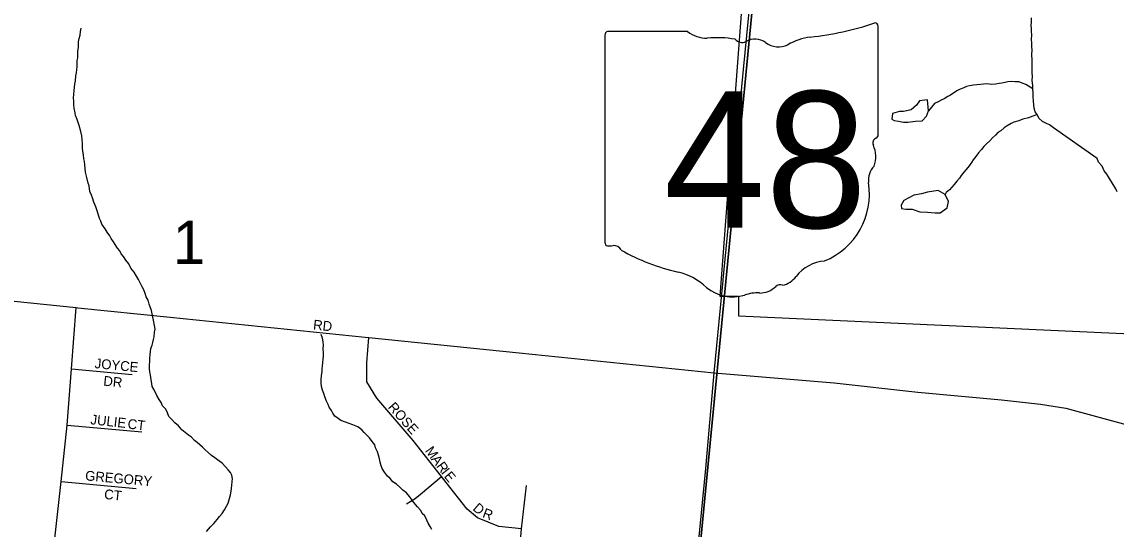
# Model space of a CAD drawing. Extents: x 0 to 1064, y 0 to 440.
# Drawn here: x 235.6 to 252.5, y 261.54 to 269.38 of the extents above; entities that cross this region are included whole.
import ezdxf

# ---------------------------------------------------------------- set-up
doc = ezdxf.new("R2010")
doc.units = 0
for name, color, linetype in [('GM_X_City_Street', 7, 'Continuous'), ('GM_X_City_Street_Text', 7, 'Continuous'), ('GM_X_Corporation', 7, 'Continuous'), ('GM_X_Minor_Lake', 7, 'Continuous'), ('GM_X_Minor_River', 7, 'Continuous'), ('GM_X_Section', 7, 'Continuous'), ('GM_X_Section_Text', 7, 'Continuous'), ('GM_X_State_Location', 7, 'Continuous'), ('GM_X_State_Route', 7, 'Continuous'), ('GM_X_State_Shield', 7, 'Continuous')]:
    doc.layers.add(name, color=color, linetype=linetype)

msp = doc.modelspace()

# ---------------------------------------------------------------- linework, layer by layer
at = {"layer": 'GM_X_City_Street'}
for points in [[(231.391, 265.48), (236.44, 264.965), (236.464, 264.962)], [(238.235, 258.707), (238.25, 258.748), (237.06, 259.196), (236.641, 259.365), (236.441, 259.452), (236.269, 259.569), (236.095, 259.825), (236.019, 260.045), (236.019, 260.414), (236.039, 260.725), (236.108, 261.4), (236.204, 262.278), (236.297, 263.152), (236.367, 264.019), (236.44, 264.965)], [(236.464, 264.962), (237.891, 264.817)], [(237.891, 264.817), (240.903, 264.51)], [(240.903, 264.51), (240.957, 264.504), (243.281, 264.267)], [(243.316, 261.548), (242.964, 261.585), (242.634, 261.72), (242.475, 261.854), (242.154, 262.266), (242.08, 262.356), (241.643, 262.912), (241.083, 263.566), (240.926, 263.818), (240.926, 264.113), (240.957, 264.504)], [(243.281, 264.267), (246.293, 263.96)], [(236.367, 264.019), (237.305, 263.93)], [(246.293, 263.96), (246.293, 263.96), (248.143, 263.801), (249.438, 263.657), (250.728, 263.54), (251.332, 263.475), (251.723, 263.41), (252.67, 263.153)], [(236.297, 263.152), (237.453, 263.047)], [(236.204, 262.278), (237.366, 262.171)], [(241.539, 261.937), (241.673, 262.019), (241.756, 262.085), (242.08, 262.356)], [(242.808, 256.231), (243.002, 258.326), (243.231, 260.605), (243.316, 261.548), (243.392, 262.217)]]:
    msp.add_lwpolyline(points, dxfattribs=at)
at = {"layer": 'GM_X_Corporation'}
msp.add_lwpolyline([(233.933, 272.908), (238.971, 272.631), (238.971, 271.725), (246.846, 271.347), (246.376, 265.143), (246.668, 265.143), (246.668, 264.837), (253.955, 264.502)], dxfattribs=at)
at = {"layer": 'GM_X_Minor_Lake'}
for points in [[(249.215, 267.994), (249.154, 267.996), (249.044, 267.962), (249.035, 267.877), (249.071, 267.858), (249.138, 267.844), (249.217, 267.83), (249.284, 267.828), (249.4, 267.844), (249.504, 267.853), (249.572, 267.925), (249.599, 268.003), (249.594, 268.064)], [(249.585, 268.174), (249.462, 268.158), (249.418, 268.093), (249.331, 268.022), (249.215, 267.994)], [(249.594, 268.064), (249.585, 268.174)], [(249.372, 266.701), (249.218, 266.619), (249.179, 266.547), (249.184, 266.498), (249.251, 266.485), (249.349, 266.488), (249.469, 266.443), (249.585, 266.44), (249.706, 266.431), (249.779, 266.429), (249.891, 266.506), (249.911, 266.603), (249.859, 266.713)], [(249.859, 266.713), (249.751, 266.777), (249.586, 266.75), (249.494, 266.722), (249.372, 266.701)]]:
    msp.add_lwpolyline(points, dxfattribs=at)
at = {"layer": 'GM_X_Minor_River'}
for points in [[(252.205, 267.268), (251.533, 267.745), (251.468, 267.789), (251.426, 267.809), (251.36, 267.841), (251.306, 267.891), (251.278, 267.947), (251.249, 267.99), (251.232, 268.045), (251.228, 268.094), (251.224, 268.161), (251.22, 268.222), (251.216, 268.277), (251.212, 268.344), (251.213, 268.392), (251.204, 268.477), (251.206, 268.538), (251.202, 268.593), (251.203, 268.641), (251.2, 268.72), (251.202, 268.793), (251.199, 268.872), (251.201, 268.945), (251.197, 268.994), (251.199, 269.06), (251.194, 269.103), (251.197, 269.182), (251.192, 269.224), (251.194, 269.273), (251.189, 269.328), (251.191, 269.376), (251.193, 269.443)], [(236.526, 267.62), (236.509, 267.687), (236.482, 267.779), (236.455, 267.871), (236.426, 267.932), (236.422, 267.975), (236.406, 268.048), (236.401, 268.097), (236.403, 268.152), (236.399, 268.206), (236.4, 268.255), (236.409, 268.321), (236.41, 268.364), (236.418, 268.424), (236.426, 268.467), (236.434, 268.545), (236.442, 268.594), (236.45, 268.642), (236.451, 268.684), (236.453, 268.739), (236.454, 268.781), (236.462, 268.824), (236.463, 268.866), (236.465, 268.927), (236.473, 268.981), (236.475, 269.03), (236.476, 269.072), (236.484, 269.121), (236.498, 269.175), (236.506, 269.229), (236.513, 269.284)], [(251.212, 268.344), (251.105, 268.414), (251.05, 268.434), (251.002, 268.453), (250.941, 268.455), (250.881, 268.457), (250.826, 268.453), (250.783, 268.442), (250.734, 268.431), (250.691, 268.426), (250.636, 268.416), (250.581, 268.412), (250.538, 268.419), (250.496, 268.42), (250.453, 268.416), (250.404, 268.411), (250.349, 268.407), (250.294, 268.402), (250.233, 268.392), (250.19, 268.381), (250.147, 268.358), (250.091, 268.342), (250.048, 268.319), (249.992, 268.284), (249.942, 268.249), (249.899, 268.226), (249.843, 268.192), (249.799, 268.169), (249.75, 268.146), (249.694, 268.117), (249.599, 268.003)], [(251.278, 267.947), (251.148, 267.896), (251.056, 267.875), (250.995, 267.852), (250.921, 267.83), (250.877, 267.807), (250.815, 267.773), (250.772, 267.744), (250.716, 267.697), (250.672, 267.668), (250.634, 267.627), (250.59, 267.586), (250.546, 267.544), (250.496, 267.497), (250.458, 267.456), (250.42, 267.409), (250.375, 267.355), (250.331, 267.302), (250.293, 267.249), (250.267, 267.207), (250.229, 267.154), (250.184, 267.1), (250.146, 267.059), (250.108, 267.005), (250.082, 266.964), (250.038, 266.917), (250, 266.869), (249.962, 266.828), (249.924, 266.786), (249.874, 266.746), (249.859, 266.713)], [(238.844, 262.217), (238.846, 262.278), (238.853, 262.32), (238.843, 262.375), (238.82, 262.418), (238.785, 262.462), (238.744, 262.505), (238.691, 262.562), (238.619, 262.613), (238.578, 262.644), (238.53, 262.682), (238.477, 262.726), (238.43, 262.77), (238.388, 262.808), (238.347, 262.846), (238.306, 262.883), (238.264, 262.915), (238.217, 262.965), (238.175, 262.997), (238.069, 263.079), (238.016, 263.141), (237.962, 263.185), (237.91, 263.242), (237.868, 263.285), (237.846, 263.341), (237.823, 263.396), (237.77, 263.446), (237.748, 263.502), (237.719, 263.545), (237.684, 263.607), (237.644, 263.693), (237.61, 263.749), (237.605, 263.791), (237.59, 263.883), (237.585, 263.926), (237.574, 263.968), (237.57, 264.023), (237.572, 264.078), (237.574, 264.139), (237.575, 264.181), (237.583, 264.241), (237.585, 264.29), (237.592, 264.332), (237.612, 264.386), (237.62, 264.429), (237.633, 264.471), (237.641, 264.513), (237.649, 264.585), (237.657, 264.634), (237.647, 264.689), (237.631, 264.774), (237.62, 264.817), (237.6, 264.921), (237.583, 264.976), (237.566, 265.019), (237.55, 265.08), (237.521, 265.13), (237.505, 265.185), (237.482, 265.24), (237.459, 265.284), (237.436, 265.327), (237.402, 265.401), (237.367, 265.45), (237.333, 265.512), (237.28, 265.574), (237.252, 265.642), (237.205, 265.698), (237.17, 265.754), (237.135, 265.798), (237.112, 265.841), (237.077, 265.884), (237.042, 265.94), (237.013, 265.983), (236.979, 266.033), (236.956, 266.076), (236.915, 266.132), (236.886, 266.182), (236.834, 266.256), (236.817, 266.299), (236.8, 266.342), (236.772, 266.428), (236.739, 266.52), (236.711, 266.594), (236.689, 266.661), (236.672, 266.704), (236.649, 266.76), (236.64, 266.845), (236.623, 266.888), (236.602, 266.974), (236.591, 267.017), (236.58, 267.059), (236.576, 267.114), (236.572, 267.169), (236.567, 267.224), (236.556, 267.266), (236.552, 267.327), (236.542, 267.382), (236.538, 267.431), (236.534, 267.504), (236.53, 267.559), (236.526, 267.62)], [(252.517, 266.755), (252.494, 266.798), (252.437, 266.891), (252.414, 266.934), (252.379, 266.984), (252.356, 267.027), (252.315, 267.077), (252.281, 267.151), (252.228, 267.213), (252.205, 267.268)], [(241.933, 261.539), (241.904, 261.582), (241.875, 261.637), (241.853, 261.681), (241.824, 261.748), (241.783, 261.786), (241.76, 261.829), (241.707, 261.886), (241.655, 261.954), (241.614, 262.004), (241.584, 262.047), (241.538, 262.103), (241.484, 262.147), (241.437, 262.191), (241.384, 262.236), (241.33, 262.274), (241.289, 262.324), (241.248, 262.361), (241.201, 262.423), (241.166, 262.479), (241.15, 262.522), (241.133, 262.577), (241.123, 262.632), (241.106, 262.687), (241.09, 262.737), (241.061, 262.798), (241.051, 262.847), (241.01, 262.897), (240.969, 262.953), (240.928, 262.997), (240.886, 263.034), (240.851, 263.078), (240.786, 263.122), (240.708, 263.155), (240.654, 263.175), (240.599, 263.195), (240.527, 263.221), (240.486, 263.253), (240.432, 263.291), (240.403, 263.335), (240.38, 263.378), (240.345, 263.427), (240.328, 263.47), (240.306, 263.52), (240.277, 263.587), (240.261, 263.637), (240.244, 263.692), (240.228, 263.747), (240.224, 263.802), (240.219, 263.856), (240.227, 263.911), (240.235, 263.977), (240.237, 264.02), (240.244, 264.062), (240.246, 264.117), (240.254, 264.171), (240.255, 264.213), (240.257, 264.268), (240.253, 264.329), (240.255, 264.384), (240.251, 264.438), (240.24, 264.493), (240.224, 264.548)], [(238.449, 261.507), (238.512, 261.578), (238.563, 261.631), (238.613, 261.69), (238.652, 261.737), (238.69, 261.785), (238.728, 261.844), (238.76, 261.898), (238.786, 261.946), (238.807, 262.018), (238.821, 262.072), (238.829, 262.132), (238.836, 262.175), (238.844, 262.217)]]:
    msp.add_lwpolyline(points, dxfattribs=at)
at = {"layer": 'GM_X_Section'}
for points in [[(247.278, 273.713), (245.391, 254.213), (229.691, 255.797), (228.85, 255.88), (230.695, 275.436)], [(264.038, 272.108), (262.096, 252.537), (261.545, 252.577), (246.002, 254.147), (245.391, 254.213), (247.278, 273.713)]]:
    msp.add_lwpolyline(points, close=True, dxfattribs=at)
at = {"layer": 'GM_X_State_Route'}
for points in [[(246.43, 265.386), (246.431, 265.394), (246.461, 265.713), (246.621, 267.356), (246.743, 268.642), (246.903, 270.274), (247.015, 271.405)], [(246.293, 263.96), (246.43, 265.386)], [(245.943, 260.162), (245.958, 260.32), (246.048, 261.321), (246.161, 262.48), (246.293, 263.96)]]:
    msp.add_lwpolyline(points, dxfattribs=at)
at = {"layer": 'GM_X_State_Shield'}
for p, q in [((245.881, 269.23), (244.646, 269.23)), ((248.823, 267.635), (248.823, 269.31)), ((244.604, 269.175), (244.604, 265.973)), ((248.822, 267.635), (248.823, 267.635))]:
    msp.add_line(p, q, dxfattribs=at)
for centre, radius, start, end in [((244.653, 269.182), 0.0489, 98.1301, 188.1301), ((246.175, 269.602), 0.474, 231.6195, 271.1119), ((247.32, 273.596), 4.474, 275.8445, 288.9065), ((248.776, 269.317), 0.047, 351.8621, 97.738), ((246.333, 267.433), 1.702, 80.4867, 94.9883), ((246.719, 269.199), 0.137, 219.7921, 297.1024), ((246.92, 268.828), 0.284, 54.4667, 119.1411), ((247.287, 269.336), 0.342, 233.8562, 294.8282), ((247.891, 268.252), 0.9, 97.3462, 120.7689), ((248.812, 267.512), 0.0727, 107.944, 210.337), ((248.773, 267.628), 0.0503, 289.6038, 7.7341), ((248.35, 267.3), 0.436, 340.033, 23.6496), ((248.991, 266.934), 0.317, 136.8065, 186.9296), ((247.571, 266.721), 1.119, 292.3089, 8.9858), ((244.653, 265.966), 0.0493, 171.9584, 258.3066), ((244.66, 266.294), 0.376, 267.339, 280.6039), ((244.737, 265.788), 0.136, 29.7484, 93.2717), ((246.45, 268.665), 3.231, 240.4129, 257.1985), ((248.043, 265.074), 0.613, 94.4031, 142.5768), ((245.487, 264.535), 1.011, 47.1842, 75.836), ((247.307, 265.223), 0.0962, 65.7517, 132.6484), ((247.266, 265.663), 0.362, 282.8732, 323.2771), ((246.58, 265.773), 0.641, 230.7004, 286.2918), ((246.951, 264.666), 0.527, 85.6951, 111.2099), ((246.998, 265.533), 0.342, 268.777, 315.5493)]:
    msp.add_arc(centre, radius, start, end, dxfattribs=at)

# ---------------------------------------------------------------- texts
at = {"layer": 'GM_X_City_Street_Text'}
for s, height, rotation, p in [('RD', 0.1515, 353.9832, (240.092, 264.629)), ('JOYCE', 0.1515, 354.6883, (236.719, 264.031)), ('DR', 0.1515, 353.9934, (236.852, 263.762)), ('ROSE', 0.1515, 311.6356, (241.244, 263.422)), ('JULIE', 0.1515, 353.8271, (236.653, 263.165)), ('CT', 0.1515, 353.2946, (237.226, 263.098)), ('M', 0.152, 305.9484, (241.819, 262.753)), ('A', 0.152, 305.9528, (241.913, 262.623)), ('GREGORY', 0.1515, 354.8823, (236.572, 262.298)), ('R', 0.152, 305.9491, (241.992, 262.516)), ('I', 0.152, 307.7359, (242.065, 262.414)), ('E', 0.152, 310.1595, (242.11, 262.356)), ('CT', 0.1515, 353.6625, (236.864, 262.012)), ('D', 0.152, 319.1759, (242.552, 261.848)), ('R', 0.152, 339.5987, (242.702, 261.731))]:
    msp.add_text(s, height=height, rotation=rotation, dxfattribs=at).set_placement(p)
at = {"layer": 'GM_X_Section_Text'}
msp.add_text('1', height=0.67, rotation=0, dxfattribs=at).set_placement((237.93, 265.637))
at = {"layer": 'GM_X_State_Location'}
for s in ['s', 'r']:
    msp.add_text(s, height=0.00303, dxfattribs=at).set_placement((246.666, 267.361))
msp.add_text('48', height=0.00303, rotation=0, dxfattribs=at).set_placement((245.903, 267.141))
at = {"layer": 'GM_X_State_Shield'}
msp.add_text('48', height=2.1094, dxfattribs=at).set_placement((245.514, 266.199))

doc.saveas('drawing.dxf')
